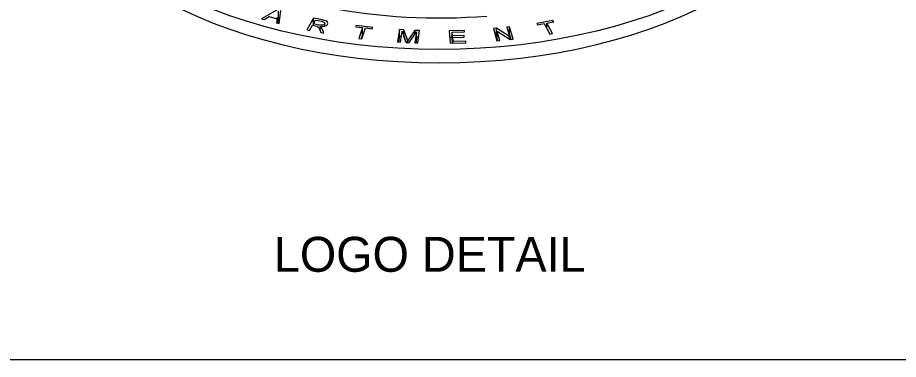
# Model space of a CAD drawing. Extents: x 99862 to 103151, y 100000 to 105076.
# Drawn here: x 101605 to 102109, y 103000 to 103195 of the extents above; entities that cross this region are included whole.
import ezdxf

# ---------------------------------------------------------------- set-up
doc = ezdxf.new("R2010")
doc.units = 0
for name, color, linetype in [('Level 1', 7, 'Continuous'), ('Level 19', 7, 'Continuous'), ('Level 20', 7, 'Continuous')]:
    doc.layers.add(name, color=color, linetype=linetype)

msp = doc.modelspace()

# ---------------------------------------------------------------- linework, layer by layer
at = {"layer": 'Level 1'}
msp.add_lwpolyline([(99862, 102999.5), (103151, 102999.5), (103151, 105075.5), (99862, 105075.5)], close=True, dxfattribs=at)
at = {"layer": 'Level 19'}
for p, q in [((101753.73, 103199.73), (101744.28, 103194.47)), ((101754.01, 103194.92), (101754.01, 103198.75)), ((101754.47, 103191.69), (101755.49, 103199.24)), ((101744.28, 103194.47), (101745.85, 103194.04)), ((101745.85, 103194.04), (101748.69, 103195.68)), ((101748.69, 103195.68), (101753.28, 103194.43)), ((101753.28, 103194.43), (101752.89, 103192.12)), ((101753.28, 103192.02), (101753.28, 103194.43)), ((101753.43, 103191.98), (101753.43, 103195.29)), ((101753.75, 103193.42), (101753.51, 103191.95)), ((101754.01, 103194.92), (101753.75, 103193.42)), ((101774.17, 103194.75), (101770.29, 103188.03)), ((101774.02, 103191.48), (101775.29, 103193.67)), ((101774.17, 103191.74), (101774.17, 103194.75)), ((101779.18, 103193.78), (101774.17, 103194.75)), ((101775.29, 103193.67), (101778.79, 103193)), ((101780.45, 103193.49), (101779.18, 103193.78)), ((101781.32, 103193.17), (101780.45, 103193.49)), ((101781.87, 103192.79), (101781.32, 103193.17)), ((101911.1, 103193.41), (101901.85, 103191.8)), ((101911.1, 103192.56), (101911.1, 103193.41)), ((101911.51, 103192.63), (101911.1, 103193.41)), ((101752.89, 103192.12), (101754.47, 103191.69)), ((101771.85, 103187.73), (101773.57, 103190.7)), ((101773.57, 103190.7), (101775.27, 103190.37)), ((101774.02, 103190.66), (101773.99, 103190.62)), ((101774.02, 103190.62), (101774.02, 103191.48)), ((101777.17, 103190.87), (101774.02, 103191.48)), ((101775.27, 103190.37), (101776.07, 103190.19)), ((101776.07, 103190.19), (101776.65, 103189.91)), ((101776.65, 103189.91), (101777.14, 103189.33)), ((101777.14, 103189.33), (101777.65, 103188.19)), ((101778.07, 103190.73), (101777.17, 103190.87)), ((101777.65, 103188.19), (101778.3, 103186.49)), ((101777.91, 103187.52), (101777.91, 103190.01)), ((101777.91, 103190.01), (101779.42, 103189.96)), ((101778.57, 103189.5), (101777.91, 103190.01)), ((101778.79, 103190.69), (101778.07, 103190.73)), ((101779.25, 103188.37), (101778.57, 103189.5)), ((101778.79, 103193), (101779.78, 103192.72)), ((101779.36, 103190.76), (101778.79, 103190.69)), ((101780.09, 103186.15), (101779.25, 103188.37)), ((101779.85, 103190.93), (101779.36, 103190.76)), ((101779.42, 103189.96), (101780.62, 103190.17)), ((101779.78, 103192.72), (101780.37, 103192.35)), ((101780.23, 103191.18), (101779.85, 103190.93)), ((101780.48, 103191.47), (101780.23, 103191.18)), ((101780.37, 103192.35), (101780.59, 103191.93)), ((101780.59, 103191.93), (101780.48, 103191.47)), ((101780.59, 103190.17), (101780.59, 103191.93)), ((101780.62, 103190.17), (101781.5, 103190.6)), ((101781.5, 103190.6), (101782.07, 103191.22)), ((101782.19, 103192.3), (101781.87, 103192.79)), ((101782.07, 103191.22), (101782.26, 103191.76)), ((101782.26, 103191.76), (101782.19, 103192.3)), ((101798.53, 103190.62), (101798.25, 103189.81)), ((101798.25, 103189.81), (101802.18, 103189.36)), ((101798.53, 103189.78), (101798.53, 103190.62)), ((101808.01, 103189.52), (101798.53, 103190.62)), ((101802.18, 103189.36), (101800.04, 103183.22)), ((101801.66, 103183.03), (101803.8, 103189.17)), ((101802.18, 103185.53), (101802.18, 103189.36)), ((101803.8, 103189.17), (101807.73, 103188.72)), ((101807.73, 103188.72), (101808.01, 103189.52)), ((101823.21, 103188.23), (101822.18, 103181.18)), ((101823.21, 103184.4), (101823.21, 103188.23)), ((101825.85, 103188.1), (101823.21, 103188.23)), ((101825.85, 103184.28), (101825.85, 103188.1)), ((101827.73, 103183.02), (101825.85, 103188.1)), ((101878.72, 103189), (101876.99, 103188.83)), ((101876.99, 103188.83), (101879.04, 103181.85)), ((101878.72, 103185.17), (101878.72, 103189)), ((101886.23, 103184.24), (101878.72, 103189)), ((101886.29, 103189.74), (101884.66, 103189.58)), ((101884.66, 103189.58), (101886.23, 103184.24)), ((101886.29, 103185.91), (101886.29, 103189.74)), ((101888.35, 103182.76), (101886.29, 103189.74)), ((101901.85, 103191.8), (101902.25, 103191.02)), ((101902.25, 103191.02), (101906.09, 103191.69)), ((101906.09, 103191.69), (101909.22, 103185.69)), ((101907.67, 103188.99), (101907.51, 103188.96)), ((101907.67, 103191.96), (101911.51, 103192.63)), ((101907.67, 103188.66), (101907.67, 103191.96)), ((101910.8, 103185.97), (101907.67, 103191.96)), ((101770.29, 103188.03), (101771.85, 103187.73)), ((101778.3, 103186.49), (101780.09, 103186.15)), ((101800.04, 103183.22), (101801.66, 103183.03)), ((101802.18, 103185.53), (101801.32, 103183.07)), ((101802.79, 103186.29), (101802.18, 103186.36)), ((101823.21, 103184.4), (101822.74, 103181.15)), ((101824.3, 103184.35), (101823.21, 103184.4)), ((101823.83, 103181.1), (101824.74, 103187.34)), ((101824.74, 103187.34), (101827.04, 103180.94)), ((101825.85, 103184.28), (101825.84, 103184.28)), ((101827.08, 103180.94), (101825.85, 103184.28)), ((101828.1, 103181.96), (101827.73, 103183.02)), ((101828.83, 103183.06), (101828.1, 103181.96)), ((101832.08, 103187.8), (101828.83, 103183.06)), ((101828.84, 103180.85), (101832.96, 103186.94)), ((101832.96, 103186.94), (101832.05, 103180.7)), ((101832.08, 103185.64), (101832.08, 103187.8)), ((101834.73, 103187.67), (101832.08, 103187.8)), ((101832.96, 103183.11), (101832.61, 103180.67)), ((101832.96, 103183.11), (101832.96, 103186.94)), ((101834.17, 103183.87), (101832.96, 103183.93)), ((101833.7, 103180.62), (101834.73, 103187.67)), ((101860.47, 103187.82), (101851.75, 103187.57)), ((101851.75, 103187.57), (101852.36, 103180.5)), ((101853.47, 103183.79), (101852.08, 103183.75)), ((101853.47, 103186.8), (101860.54, 103187)), ((101853.47, 103182.97), (101853.47, 103186.8)), ((101853.65, 103184.62), (101853.47, 103186.8)), ((101860.25, 103184.81), (101853.65, 103184.62)), ((101853.65, 103180.79), (101853.65, 103184.62)), ((101853.72, 103183.81), (101860.32, 103183.99)), ((101853.72, 103180.53), (101853.72, 103183.81)), ((101853.93, 103181.36), (101853.72, 103183.81)), ((101860.25, 103183.99), (101860.25, 103184.81)), ((101860.32, 103183.99), (101860.25, 103184.81)), ((101860.47, 103187), (101860.47, 103187.82)), ((101860.54, 103187), (101860.47, 103187.82)), ((101878.72, 103185.17), (101878.08, 103185.11)), ((101879.1, 103184.93), (101878.72, 103185.17)), ((101879.1, 103183.52), (101879.1, 103187.35)), ((101880.67, 103182.01), (101879.1, 103187.35)), ((101879.1, 103187.35), (101886.62, 103182.59)), ((101879.58, 103181.9), (101879.1, 103183.52)), ((101886.29, 103185.91), (101885.76, 103185.86)), ((101886.23, 103182.83), (101886.23, 103184.24)), ((101887.25, 103182.65), (101886.29, 103185.91)), ((101909.22, 103185.69), (101910.8, 103185.97)), ((101822.18, 103181.18), (101823.83, 103181.1)), ((101827.04, 103180.94), (101828.84, 103180.85)), ((101828.1, 103180.89), (101828.1, 103181.96)), ((101832.05, 103180.7), (101833.7, 103180.62)), ((101852.36, 103180.5), (101861.31, 103180.75)), ((101853.65, 103180.79), (101853.47, 103182.97)), ((101853.72, 103180.8), (101853.65, 103180.79)), ((101861.24, 103181.57), (101853.93, 103181.36)), ((101853.93, 103180.54), (101853.93, 103181.36)), ((101861.24, 103180.75), (101861.24, 103181.57)), ((101861.31, 103180.75), (101861.24, 103181.57)), ((101879.04, 103181.85), (101880.67, 103182.01)), ((101886.62, 103182.59), (101888.35, 103182.76))]:
    msp.add_line(p, q, dxfattribs=at)
msp.add_ellipse((101846.07, 103310.38), major_axis=(231.25, 0), ratio=0.57735, dxfattribs=at)
for centre, major_axis, start_param, end_param in [((101846.07, 103302.72), (231.25, 0), 3.141593, 6.28318), ((101846.07, 103310.38), (200, 0), 3.927048, 4.849057)]:
    msp.add_ellipse(centre, major_axis=major_axis, ratio=0.57735, start_param=start_param, end_param=end_param, dxfattribs=at)

# ---------------------------------------------------------------- texts
at = {"layer": 'Level 20'}
msp.add_text('LOGO DETAIL', height=20, dxfattribs=at).set_placement((101751.41, 103049.64))

doc.saveas('drawing.dxf')
